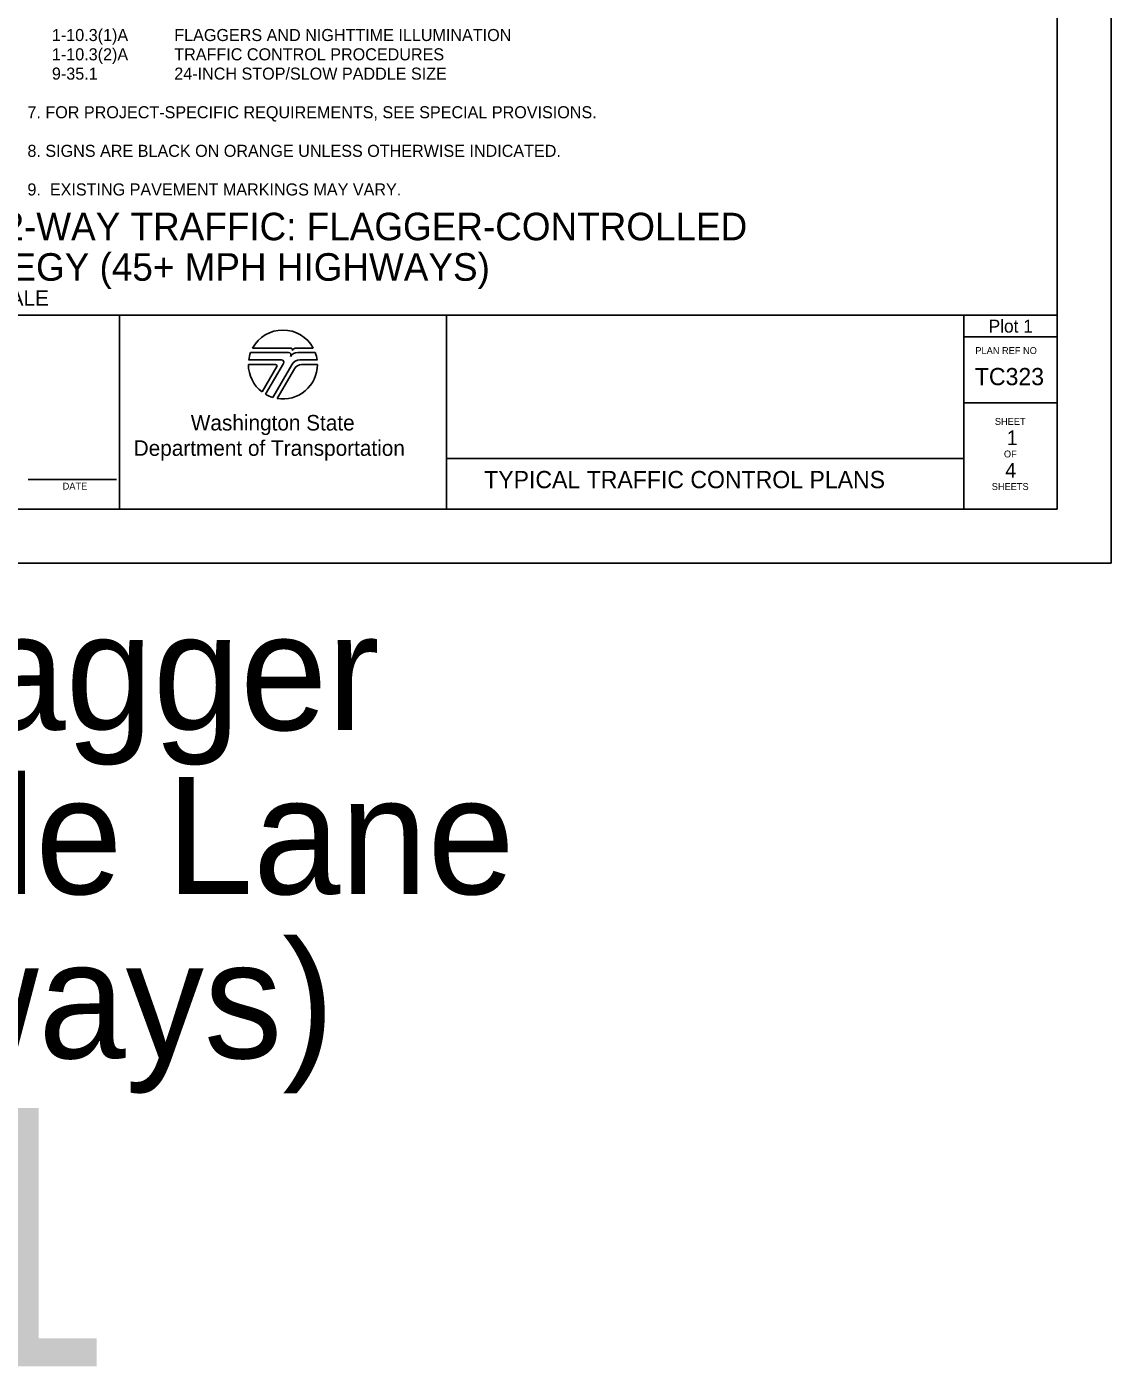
# Model space of a CAD drawing. Extents: x 99999.1 to 100095.7, y 99995 to 100010.7.
# Drawn here: x 100009.77 to 100016.06, y 99995.01 to 100002.8 of the extents above; entities that cross this region are included whole.
import ezdxf

# ---------------------------------------------------------------- set-up
doc = ezdxf.new("R2010")
doc.units = 0
for name, color, linetype in [('SH_DE_DetailHeading1Text', 7, 'Continuous'), ('SH_GI_GeneralNotesBodyText', 7, 'Continuous'), ('SH_GI_PlotLimits', 7, 'Continuous'), ('SH_GI_SheetBorder', 7, 'Continuous'), ('SH_GI_SheetLocationText', 7, 'Continuous'), ('SH_GI_SheetTextInCells', 7, 'Continuous'), ('SH_GI_TitleBlockText', 7, 'Continuous'), ('SH_GI_WSDOTLogo', 7, 'Continuous')]:
    doc.layers.add(name, color=color, linetype=linetype)

msp = doc.modelspace()

# ---------------------------------------------------------------- linework, layer by layer
at = {"layer": 'SH_GI_PlotLimits'}
msp.add_lwpolyline([(99999.0625, 99999.6875), (100016.0625, 99999.6875), (100016.0625, 100010.6875), (99999.0625, 100010.6875)], close=True, dxfattribs=at)
at = {"layer": 'SH_GI_SheetBorder'}
for p, q in [((100015.75, 100010.375), (100015.75, 100000)), ((100000, 100001.1259), (100015.75, 100001.1259)), ((100010.3089, 100001.1259), (100010.3089, 100000)), ((100012.2055, 100001.1259), (100012.2055, 100000)), ((100015.2079, 100001.1259), (100015.2079, 100000)), ((100015.2079, 100001.0008), (100015.75, 100001.0008)), ((100015.2079, 100000.6176), (100015.75, 100000.6176)), ((100012.2055, 100000.2955), (100015.2079, 100000.2955)), ((100009.7797, 100000.1733), (100010.2914, 100000.1733)), ((100000, 100000), (100015.75, 100000))]:
    msp.add_line(p, q, dxfattribs=at)
at = {"layer": 'SH_GI_WSDOTLogo'}
for p, q in [((100011.2894, 100000.9094), (100011.0697, 100000.9094)), ((100011.303, 100000.9354), (100011.0815, 100000.9354)), ((100011.433, 100000.9354), (100011.3351, 100000.9354)), ((100011.343, 100000.9094), (100011.3429, 100000.9094)), ((100011.4448, 100000.9094), (100011.343, 100000.9094)), ((100011.0572, 100000.84), (100011.2148, 100000.84)), ((100011.059, 100000.8661), (100011.2496, 100000.8661)), ((100011.261, 100000.8464), (100011.1567, 100000.6672)), ((100011.1989, 100000.6487), (100011.3089, 100000.839)), ((100011.3558, 100000.8661), (100011.4555, 100000.8661)), ((100011.3655, 100000.8394), (100011.4572, 100000.8394)), ((100011.222, 100000.8277), (100011.1364, 100000.6807)), ((100011.2244, 100000.6428), (100011.3242, 100000.8156))]:
    msp.add_line(p, q, dxfattribs=at)
for centre, radius, start, end in [((100011.2572, 100000.84), 0.2, 28.47865, 151.53204), ((100011.2572, 100000.84), 0.2, 159.69598, 172.50569), ((100011.2894, 100000.8946), 0.0148, 327.8418, 89.99855), ((100011.3429, 100000.861), 0.0484, 89.99529, 147.82376), ((100011.303, 100000.9263), 0.00903, 329.87418, 90.00328), ((100011.3352, 100000.9066), 0.0287, 90.00721, 148.16763), ((100011.2572, 100000.84), 0.2, 7.49431, 20.29406), ((100011.2572, 100000.84), 0.2, 179.99864, 232.84327), ((100011.2149, 100000.8318), 0.0082, 329.74356, 90), ((100011.2572, 100000.84), 0.2, 260.54554, 359.80857), ((100011.2497, 100000.853), 0.0131, 329.76834, 90), ((100011.3558, 100000.8119), 0.0542, 90, 149.99738), ((100011.3654, 100000.7918), 0.0476, 90, 150.05432), ((100011.2572, 100000.84), 0.2, 239.79292, 253.0448)]:
    msp.add_arc(centre, radius, start, end, dxfattribs=at)

# ---------------------------------------------------------------- texts
at = {"layer": 'SH_DE_DetailHeading1Text'}
for s, height, p in [('PILOT CAR OPERATION FOR ALTERNATING 1-LANE, 2-WAY TRAFFIC: FLAGGER-CONTROLLED', 0.16, (100004.1912, 100001.5606)), ('SHARED BIKE-VEHICLE LANE STRATEGY (45+ MPH HIGHWAYS)', 0.16, (100005.8775, 100001.3259)), ('NOT TO SCALE', 0.09, (100009.0168, 100001.1809))]:
    msp.add_text(s, height=height, rotation=360, dxfattribs=at).set_placement(p)
at = {"layer": 'SH_GI_GeneralNotesBodyText'}
for s, p in [('1-10.3(1)A ', (100009.9171, 100002.7166)), ('FLAGGERS AND NIGHTTIME ILLUMINATION', (100010.6271, 100002.7166)), ('1-10.3(2)A', (100009.9171, 100002.6046)), ('TRAFFIC CONTROL PROCEDURES', (100010.6271, 100002.6046)), ('9-35.1', (100009.9171, 100002.4926)), ('24-INCH STOP/SLOW PADDLE SIZE', (100010.6271, 100002.4926)), ('7. FOR PROJECT-SPECIFIC REQUIREMENTS, SEE SPECIAL PROVISIONS.', (100009.7751, 100002.2686)), ('8. SIGNS ARE BLACK ON ORANGE UNLESS OTHERWISE INDICATED.', (100009.7751, 100002.0446)), ('9.  EXISTING PAVEMENT MARKINGS MAY VARY.', (100009.7751, 100001.8206))]:
    msp.add_text(s, height=0.07, rotation=360, dxfattribs=at).set_placement(p)
at = {"layer": 'SH_GI_SheetBorder'}
msp.add_text('PLAN REF NO', height=0.040032, dxfattribs=at).set_placement((100015.2747, 100000.9008))
at = {"layer": 'SH_GI_SheetLocationText'}
for s, height, p in [('Plot 1', 0.075, (100015.3518, 100001.025)), ('Pilot Car Op: Flagger', 0.68, (100003.2766, 99998.7191)), ('Shared Bike-Vehicle Lane', 0.68, (100002.0877, 99997.7671)), ('(45+ mph Highways)', 0.68, (100003.1924, 99996.8151)), ('Plot 1', 1.5, (100005.1448, 99995.0267))]:
    msp.add_text(s, height=height, dxfattribs=at).set_placement(p)
at = {"layer": 'SH_GI_SheetTextInCells'}
for s, height, p in [('Washington State', 0.090072, (100010.7229, 100000.4571)), ('SHEET', 0.04003, (100015.3877, 100000.4896)), ('Department of Transportation', 0.090072, (100010.3916, 100000.3101)), ('OF', 0.04003, (100015.4406, 100000.3008)), ('DATE', 0.04003, (100009.9794, 100000.1141)), ('SHEETS', 0.04003, (100015.3698, 100000.112))]:
    msp.add_text(s, height=height, dxfattribs=at).set_placement(p)
at = {"layer": 'SH_GI_TitleBlockText'}
for s, height, p in [('TC323', 0.1, (100015.2718, 100000.72)), ('1', 0.085, (100015.4566, 100000.3723)), ('TYPICAL TRAFFIC CONTROL PLANS', 0.1, (100012.4251, 100000.1224)), ('4', 0.085, (100015.4485, 100000.1843))]:
    msp.add_text(s, height=height, dxfattribs=at).set_placement(p)

doc.saveas('drawing.dxf')
